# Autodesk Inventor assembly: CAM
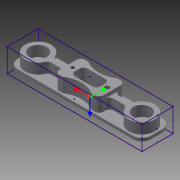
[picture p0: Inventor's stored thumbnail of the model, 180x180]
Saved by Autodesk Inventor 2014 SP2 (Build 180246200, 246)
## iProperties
Created: 2005-05
Part Number: CAM
Document SubType Name: Assembly
Designer: Administrator
Mass: 43.9253 g
Surface Area: 202.838 cm^2
Volume: 43.9253 cm^3
Density: 1 g/cm^3
Author: Administrator
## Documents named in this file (3)
- C:\Users\e_krauts\AppData\Local\SolidCAM Temporary Files\SEITENTEIL1\SEITENTEIL1.IAM
- C:\Users\e_krauts\AppData\Local\SolidCAM Temporary Files\SEITENTEIL1\DesignModel.ipt
- C:\Users\e_krauts\AppData\Local\SolidCAM Temporary Files\SEITENTEIL1\CAM.IPT
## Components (2 placed, 2 different names)
1. DesignModel:1
2. CAM:1
